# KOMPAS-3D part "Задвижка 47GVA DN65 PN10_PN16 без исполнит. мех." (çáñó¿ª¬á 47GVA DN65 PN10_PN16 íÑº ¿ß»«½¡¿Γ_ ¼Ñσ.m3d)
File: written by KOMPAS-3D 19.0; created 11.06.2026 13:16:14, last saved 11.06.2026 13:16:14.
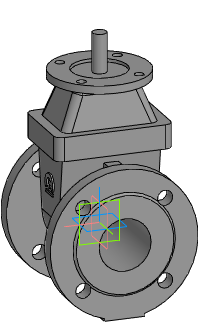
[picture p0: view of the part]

Document properties: Автор: Евгений; Полное имя файла: Z:\3.Личные\kachalov\001_3d для проектировщиков\2.2 Тип 47GVA, 47GVA.Z\_stp\_stp_Задвижка 47GVA DN40-DN1000 без исп.мех\Задвижка 47GVA DN65 PN10_PN16 без исполнит_ мех.m3d

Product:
- Part/product: Задвижка 47GVA DN65 PN10_PN16 без исполнит. мех.

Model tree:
1. Операция без истории:1  (labels: Задвижка 47GVA DN65 PN10_PN16 без исполнит. мех.)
